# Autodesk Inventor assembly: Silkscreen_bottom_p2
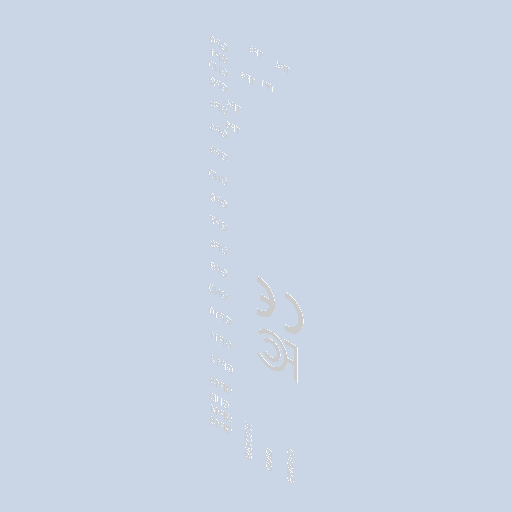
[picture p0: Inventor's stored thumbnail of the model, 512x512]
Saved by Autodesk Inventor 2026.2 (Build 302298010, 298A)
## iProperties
Created: 2026-10
Part Number: Silkscreen_bottom_p2
Document SubType Name: Assembly
Designer: mel
Author: mel
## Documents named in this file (32)
- D:\travail\année 2026-2027\1 sti2d IT\poubelle à verre\raspberry-pico-2-microcontroller-rp2350-1.snapshot.5\raspberry_pico_2\raspberry_pico_2\Silkscreen_bottom_p2.iam
- D:\travail\année 2026-2027\1 sti2d IT\poubelle à verre\raspberry-pico-2-microcontroller-rp2350-1.snapshot.5\raspberry_pico_2\raspberry_pico_2\Text_GP0.ipt
- D:\travail\année 2026-2027\1 sti2d IT\poubelle à verre\raspberry-pico-2-microcontroller-rp2350-1.snapshot.5\raspberry_pico_2\raspberry_pico_2\Text_GP1.ipt
- D:\travail\année 2026-2027\1 sti2d IT\poubelle à verre\raspberry-pico-2-microcontroller-rp2350-1.snapshot.5\raspberry_pico_2\raspberry_pico_2\Text_GND003.ipt
- D:\travail\année 2026-2027\1 sti2d IT\poubelle à verre\raspberry-pico-2-microcontroller-rp2350-1.snapshot.5\raspberry_pico_2\raspberry_pico_2\Text_GP2.ipt
- D:\travail\année 2026-2027\1 sti2d IT\poubelle à verre\raspberry-pico-2-microcontroller-rp2350-1.snapshot.5\raspberry_pico_2\raspberry_pico_2\Text_GP3.ipt
- D:\travail\année 2026-2027\1 sti2d IT\poubelle à verre\raspberry-pico-2-microcontroller-rp2350-1.snapshot.5\raspberry_pico_2\raspberry_pico_2\Text_GP4.ipt
- D:\travail\année 2026-2027\1 sti2d IT\poubelle à verre\raspberry-pico-2-microcontroller-rp2350-1.snapshot.5\raspberry_pico_2\raspberry_pico_2\Text_GP5.ipt
- D:\travail\année 2026-2027\1 sti2d IT\poubelle à verre\raspberry-pico-2-microcontroller-rp2350-1.snapshot.5\raspberry_pico_2\raspberry_pico_2\Text_GND_004.ipt
- D:\travail\année 2026-2027\1 sti2d IT\poubelle à verre\raspberry-pico-2-microcontroller-rp2350-1.snapshot.5\raspberry_pico_2\raspberry_pico_2\Text_GP6.ipt
- D:\travail\année 2026-2027\1 sti2d IT\poubelle à verre\raspberry-pico-2-microcontroller-rp2350-1.snapshot.5\raspberry_pico_2\raspberry_pico_2\Text_GP7.ipt
- D:\travail\année 2026-2027\1 sti2d IT\poubelle à verre\raspberry-pico-2-microcontroller-rp2350-1.snapshot.5\raspberry_pico_2\raspberry_pico_2\Text_GP8.ipt
- D:\travail\année 2026-2027\1 sti2d IT\poubelle à verre\raspberry-pico-2-microcontroller-rp2350-1.snapshot.5\raspberry_pico_2\raspberry_pico_2\Text_GP9.ipt
- D:\travail\année 2026-2027\1 sti2d IT\poubelle à verre\raspberry-pico-2-microcontroller-rp2350-1.snapshot.5\raspberry_pico_2\raspberry_pico_2\Text_GND005.ipt
- D:\travail\année 2026-2027\1 sti2d IT\poubelle à verre\raspberry-pico-2-microcontroller-rp2350-1.snapshot.5\raspberry_pico_2\raspberry_pico_2\Text_GP10.ipt
- D:\travail\année 2026-2027\1 sti2d IT\poubelle à verre\raspberry-pico-2-microcontroller-rp2350-1.snapshot.5\raspberry_pico_2\raspberry_pico_2\Text_GP11.ipt
- D:\travail\année 2026-2027\1 sti2d IT\poubelle à verre\raspberry-pico-2-microcontroller-rp2350-1.snapshot.5\raspberry_pico_2\raspberry_pico_2\Text_GP12.ipt
- D:\travail\année 2026-2027\1 sti2d IT\poubelle à verre\raspberry-pico-2-microcontroller-rp2350-1.snapshot.5\raspberry_pico_2\raspberry_pico_2\Text_GP13.ipt
- D:\travail\année 2026-2027\1 sti2d IT\poubelle à verre\raspberry-pico-2-microcontroller-rp2350-1.snapshot.5\raspberry_pico_2\raspberry_pico_2\Text_GND006.ipt
- D:\travail\année 2026-2027\1 sti2d IT\poubelle à verre\raspberry-pico-2-microcontroller-rp2350-1.snapshot.5\raspberry_pico_2\raspberry_pico_2\Text_GP14.ipt
- D:\travail\année 2026-2027\1 sti2d IT\poubelle à verre\raspberry-pico-2-microcontroller-rp2350-1.snapshot.5\raspberry_pico_2\raspberry_pico_2\Text_GP15.ipt
- D:\travail\année 2026-2027\1 sti2d IT\poubelle à verre\raspberry-pico-2-microcontroller-rp2350-1.snapshot.5\raspberry_pico_2\raspberry_pico_2\Text_SWDIO.ipt
- D:\travail\année 2026-2027\1 sti2d IT\poubelle à verre\raspberry-pico-2-microcontroller-rp2350-1.snapshot.5\raspberry_pico_2\raspberry_pico_2\Text_GND007.ipt
- D:\travail\année 2026-2027\1 sti2d IT\poubelle à verre\raspberry-pico-2-microcontroller-rp2350-1.snapshot.5\raspberry_pico_2\raspberry_pico_2\Text_SWCLK.ipt
- D:\travail\année 2026-2027\1 sti2d IT\poubelle à verre\raspberry-pico-2-microcontroller-rp2350-1.snapshot.5\raspberry_pico_2\raspberry_pico_2\Text_TP2.ipt
- D:\travail\année 2026-2027\1 sti2d IT\poubelle à verre\raspberry-pico-2-microcontroller-rp2350-1.snapshot.5\raspberry_pico_2\raspberry_pico_2\Text_TP3.ipt
- D:\travail\année 2026-2027\1 sti2d IT\poubelle à verre\raspberry-pico-2-microcontroller-rp2350-1.snapshot.5\raspberry_pico_2\raspberry_pico_2\Text_TP4.ipt
- D:\travail\année 2026-2027\1 sti2d IT\poubelle à verre\raspberry-pico-2-microcontroller-rp2350-1.snapshot.5\raspberry_pico_2\raspberry_pico_2\Text_TP1.ipt
- D:\travail\année 2026-2027\1 sti2d IT\poubelle à verre\raspberry-pico-2-microcontroller-rp2350-1.snapshot.5\raspberry_pico_2\raspberry_pico_2\Text_TP5.ipt
- D:\travail\année 2026-2027\1 sti2d IT\poubelle à verre\raspberry-pico-2-microcontroller-rp2350-1.snapshot.5\raspberry_pico_2\raspberry_pico_2\Text_TP6.ipt
- D:\travail\année 2026-2027\1 sti2d IT\poubelle à verre\raspberry-pico-2-microcontroller-rp2350-1.snapshot.5\raspberry_pico_2\raspberry_pico_2\CE_logo.ipt
- D:\travail\année 2026-2027\1 sti2d IT\poubelle à verre\raspberry-pico-2-microcontroller-rp2350-1.snapshot.5\raspberry_pico_2\raspberry_pico_2\FCC_logo.ipt
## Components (31 placed, 31 different names)
1. 2814
2. 2815
3. 2816
4. 2817
5. 2818
6. 2819
7. 2820
8. 2821
9. 2822
10. 2823
11. 2824
12. 2825
13. 2826
14. 2827
15. 2828
16. 2829
17. 2830
18. 2831
19. 2832
20. 2833
21. 2834
22. 2835
23. 2836
24. 2837
25. 2838
26. 2839
27. 2840
28. 2841
29. 2842
30. 2843
31. 2844
